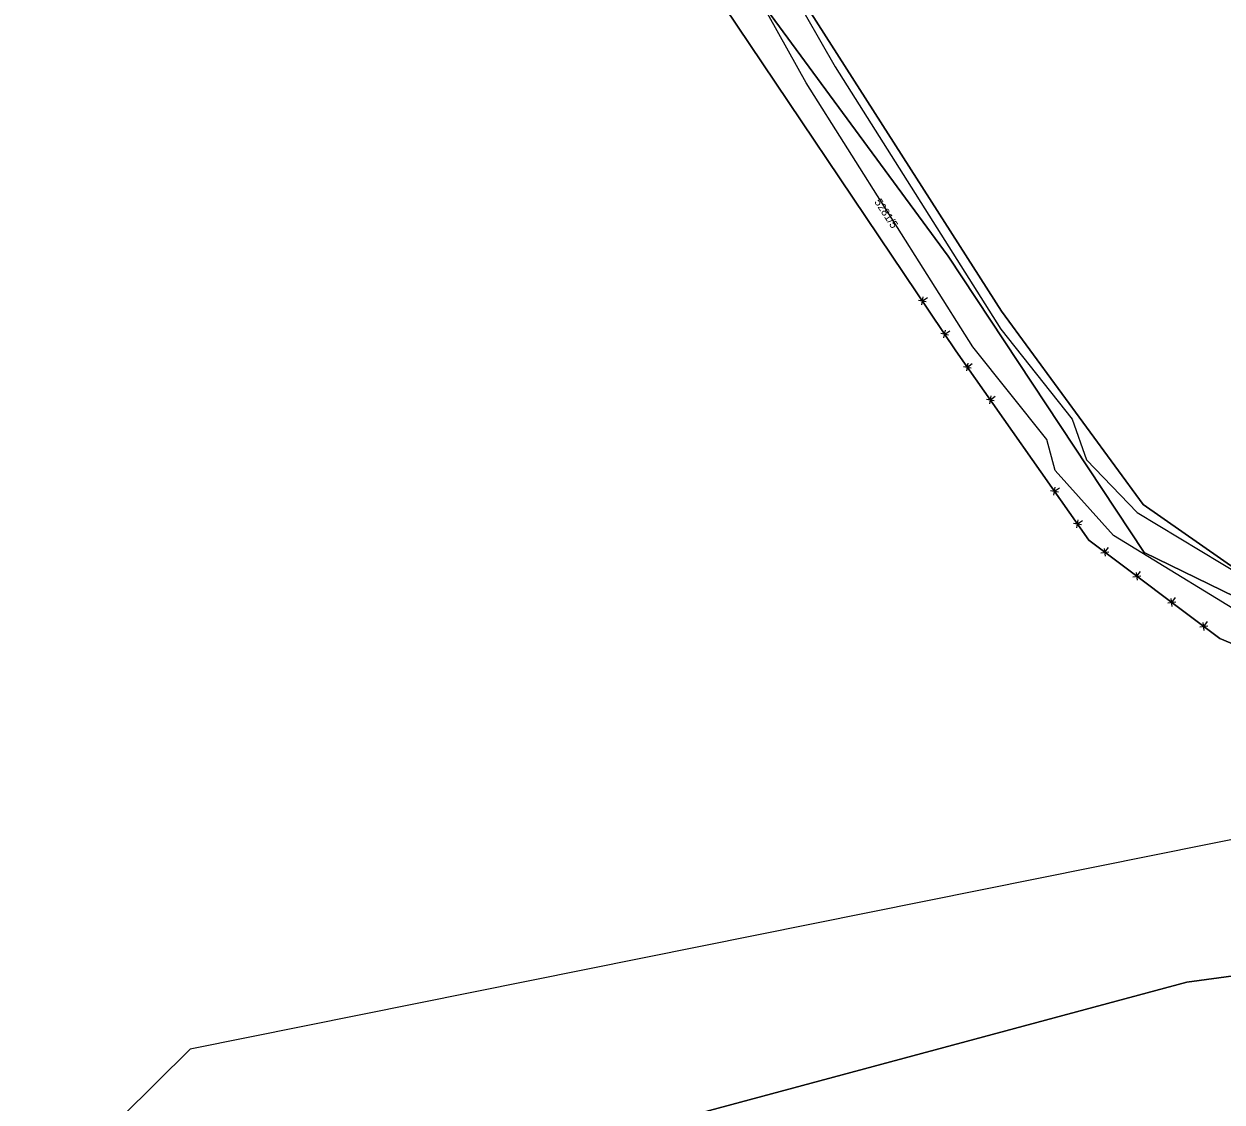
# Model space of a CAD drawing. Extents: x -439750 to -439180, y -1258684 to -1258308.
# Drawn here: x -439667.2 to -439607.3, y -1258619.8 to -1258565.9 of the extents above; entities that cross this region are included whole.
import ezdxf

# ---------------------------------------------------------------- set-up
doc = ezdxf.new("R2010")
doc.units = 0
for name, color, linetype in [('KATASTER', 7, 'Continuous'), ('TARCHY', 7, 'Continuous'), ('UOV', 7, 'Continuous')]:
    doc.layers.add(name, color=color, linetype=linetype)

# ---------------------------------------------------------------- blocks, each defined once
blk = doc.blocks.new('2072')
for p, q in [((-4.3, 0.7), (-5.7, -0.7)), ((-5.7, 0.7), (-4.3, -0.7)), ((-5, 0), (-5, -1.5)), ((4.3, 0.7), (5.7, -0.7)), ((5.7, 0.7), (4.3, -0.7)), ((5, 0), (5, -1.5))]:
    blk.add_line(p, q)

msp = doc.modelspace()

# ---------------------------------------------------------------- linework, layer by layer
at = {"layer": 'KATASTER'}
for points in [[(-439704.8, -1258494.65), (-439703.92, -1258521.17), (-439680.15, -1258515.08), (-439678.62, -1258514.6), (-439678.78, -1258516.82), (-439677.23, -1258536.72), (-439666.64, -1258532.76), (-439664.94, -1258530.22), (-439663.93, -1258528.71), (-439662.82, -1258519.84), (-439661.31, -1258521.55), (-439655.18, -1258528.47), (-439644.01, -1258541.08), (-439634.09, -1258562.13), (-439620.57, -1258582.24), (-439613.92, -1258591.72), (-439607.38, -1258596.63), (-439587.97, -1258604.8), (-439561.36, -1258613.95), (-439535.34, -1258619.8)], [(-439535.34, -1258619.8), (-439561.36, -1258613.95), (-439587.97, -1258604.8), (-439607.38, -1258596.63), (-439613.92, -1258591.72), (-439620.57, -1258582.24), (-439634.09, -1258562.13), (-439644.01, -1258541.08), (-439655.18, -1258528.47), (-439661.31, -1258521.55), (-439662.82, -1258519.84), (-439663.93, -1258528.71), (-439664.94, -1258530.22), (-439666.64, -1258532.76), (-439677.23, -1258536.72), (-439678.78, -1258516.82), (-439678.62, -1258514.6), (-439680.15, -1258515.08), (-439703.92, -1258521.17), (-439704.8, -1258494.65)], [(-439662.28, -1258501.2), (-439658.45, -1258512.88), (-439640.46, -1258538.63), (-439631.04, -1258560.29), (-439618.29, -1258580.27), (-439611.21, -1258589.93), (-439605.4, -1258593.99), (-439586.79, -1258602.08), (-439560.33, -1258610.77), (-439542.1, -1258617.55)], [(-439535.34, -1258619.8), (-439561.36, -1258613.95), (-439587.97, -1258604.8), (-439607.38, -1258596.63), (-439613.92, -1258591.72), (-439620.57, -1258582.24), (-439634.09, -1258562.13), (-439644.01, -1258541.08), (-439648.8, -1258533.92), (-439660.49, -1258516.44), (-439665.91, -1258502.4)], [(-439677.23, -1258536.72), (-439666.64, -1258532.76), (-439664.94, -1258530.22), (-439663.33, -1258528.7), (-439661.31, -1258521.55), (-439655.18, -1258528.47), (-439644.01, -1258541.08), (-439634.09, -1258562.13), (-439620.57, -1258582.24), (-439613.92, -1258591.72), (-439607.38, -1258596.63), (-439587.97, -1258604.8), (-439561.36, -1258613.95), (-439585.52, -1258610.63), (-439609.02, -1258613.81), (-439634.87, -1258620.76), (-439655.28, -1258632.7), (-439678.79, -1258645.12)], [(-439678.79, -1258645.12), (-439655.28, -1258632.7), (-439634.87, -1258620.76), (-439609.02, -1258613.81), (-439585.52, -1258610.63), (-439561.36, -1258613.95), (-439563.26, -1258617.5), (-439564.31, -1258622.49), (-439568.05, -1258628.83), (-439586.9, -1258619.84), (-439609.13, -1258622.7), (-439631.71, -1258628.28), (-439654.59, -1258643.31), (-439677.39, -1258653.86)]]:
    msp.add_lwpolyline(points, dxfattribs=at)
msp.add_lwpolyline([(-439640.46, -1258538.63), (-439597.45, -1258561.13), (-439567.51, -1258574.36), (-439550.54, -1258581.84), (-439518.67, -1258591.95), (-439482.75, -1258611.76), (-439438.12, -1258627.38), (-439494.8, -1258628.92), (-439535.34, -1258619.8), (-439542.1, -1258617.55), (-439560.33, -1258610.77), (-439586.79, -1258602.08), (-439605.4, -1258593.99), (-439611.21, -1258589.93), (-439618.29, -1258580.27), (-439631.04, -1258560.29)], close=True, dxfattribs=at)
at = {"layer": 'TARCHY'}
msp.add_lwpolyline([(-439644.01, -1258537.85), (-439641.56, -1258538.39), (-439640.46, -1258538.63), (-439631.04, -1258560.29), (-439618.29, -1258580.27), (-439611.21, -1258589.93), (-439605.4, -1258593.99), (-439586.79, -1258602.08), (-439573.1, -1258606.58), (-439571.93, -1258607.2), (-439561.97, -1258612.45), (-439564.63, -1258611.53), (-439578.21, -1258606.73), (-439592.11, -1258601.94), (-439605, -1258596.18), (-439612.69, -1258591.48), (-439615.6, -1258588.24), (-439616.03, -1258586.69), (-439619.73, -1258582.05), (-439628.05, -1258568.85), (-439634.58, -1258557.15), (-439641.64, -1258541.07)], close=True, dxfattribs=at)
msp.add_lwpolyline([(-439641.56, -1258538.39), (-439640.31, -1258540.09), (-439633.07, -1258556.48), (-439631.04, -1258560.29), (-439626.6, -1258568.05), (-439618.33, -1258581.17), (-439614.75, -1258585.66), (-439614.04, -1258587.7), (-439611.5, -1258590.33), (-439604.15, -1258594.77), (-439591.44, -1258600.43), (-439586.79, -1258602.08), (-439577.67, -1258605.17), (-439571.93, -1258607.2)], dxfattribs=at)
at = {"layer": 'UOV'}
for points in [[(-439677.23, -1258536.72), (-439666.64, -1258532.76), (-439664.94, -1258530.22), (-439663.33, -1258528.7), (-439661.31, -1258521.55), (-439644.01, -1258541.08), (-439634.09, -1258562.13), (-439620.57, -1258582.24), (-439613.92, -1258591.72), (-439607.38, -1258596.63), (-439591.01, -1258603.52), (-439658.86, -1258617.16), (-439684.54, -1258642.58), (-439686.09, -1258644.61), (-439698.51, -1258643.74), (-439717.85, -1258616.24), (-439718.4, -1258599.9), (-439713.55, -1258578.29), (-439704.98, -1258583.43), (-439700.34, -1258583.24), (-439692.23, -1258576.64), (-439685.44, -1258555.87), (-439684.77, -1258547.23), (-439677.24, -1258536.55)], [(-439632.35, -1258562), (-439620.95, -1258577.51), (-439611.16, -1258592.34), (-439589.02, -1258603.12), (-439591.01, -1258603.52), (-439607.38, -1258596.63), (-439613.92, -1258591.72), (-439620.57, -1258582.24), (-439634.09, -1258562.13), (-439644.01, -1258541.08), (-439648.8, -1258533.92), (-439645.84, -1258537.45)], [(-439640.46, -1258538.63), (-439631.04, -1258560.29), (-439618.29, -1258580.27), (-439611.21, -1258589.93), (-439605.4, -1258593.99), (-439586.79, -1258602.08), (-439573.1, -1258606.58), (-439557.46, -1258614.83), (-439561.36, -1258613.95), (-439581.17, -1258607.14), (-439589.02, -1258603.12), (-439611.16, -1258592.34), (-439620.95, -1258577.51), (-439632.35, -1258562), (-439645.84, -1258537.45)]]:
    msp.add_lwpolyline(points, close=True, dxfattribs=at)

# ---------------------------------------------------------------- block references
at = {"layer": 'KATASTER', "xscale": 0.2}
for p, yscale, rotation in [((-439621.686, -1258580.58), 0.20000000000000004, 123.930771), ((-439619.421, -1258583.877), 0.19999999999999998, 125.076687), ((-439615.069, -1258590.083), 0.19999999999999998, 125.076687), ((-439612.321, -1258592.921), 0.19999999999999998, 143.12485700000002), ((-439608.979, -1258595.429), 0.19999999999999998, 143.12485700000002)]:
    msp.add_blockref('2072', p, dxfattribs=dict(at, yscale=yscale, rotation=rotation))

# ---------------------------------------------------------------- texts
at = {"layer": 'UOV'}
msp.add_text('5281/5', height=0.4, rotation=303.496, dxfattribs=at).set_placement((-439624.666, -1258574.804))

doc.saveas('drawing.dxf')
